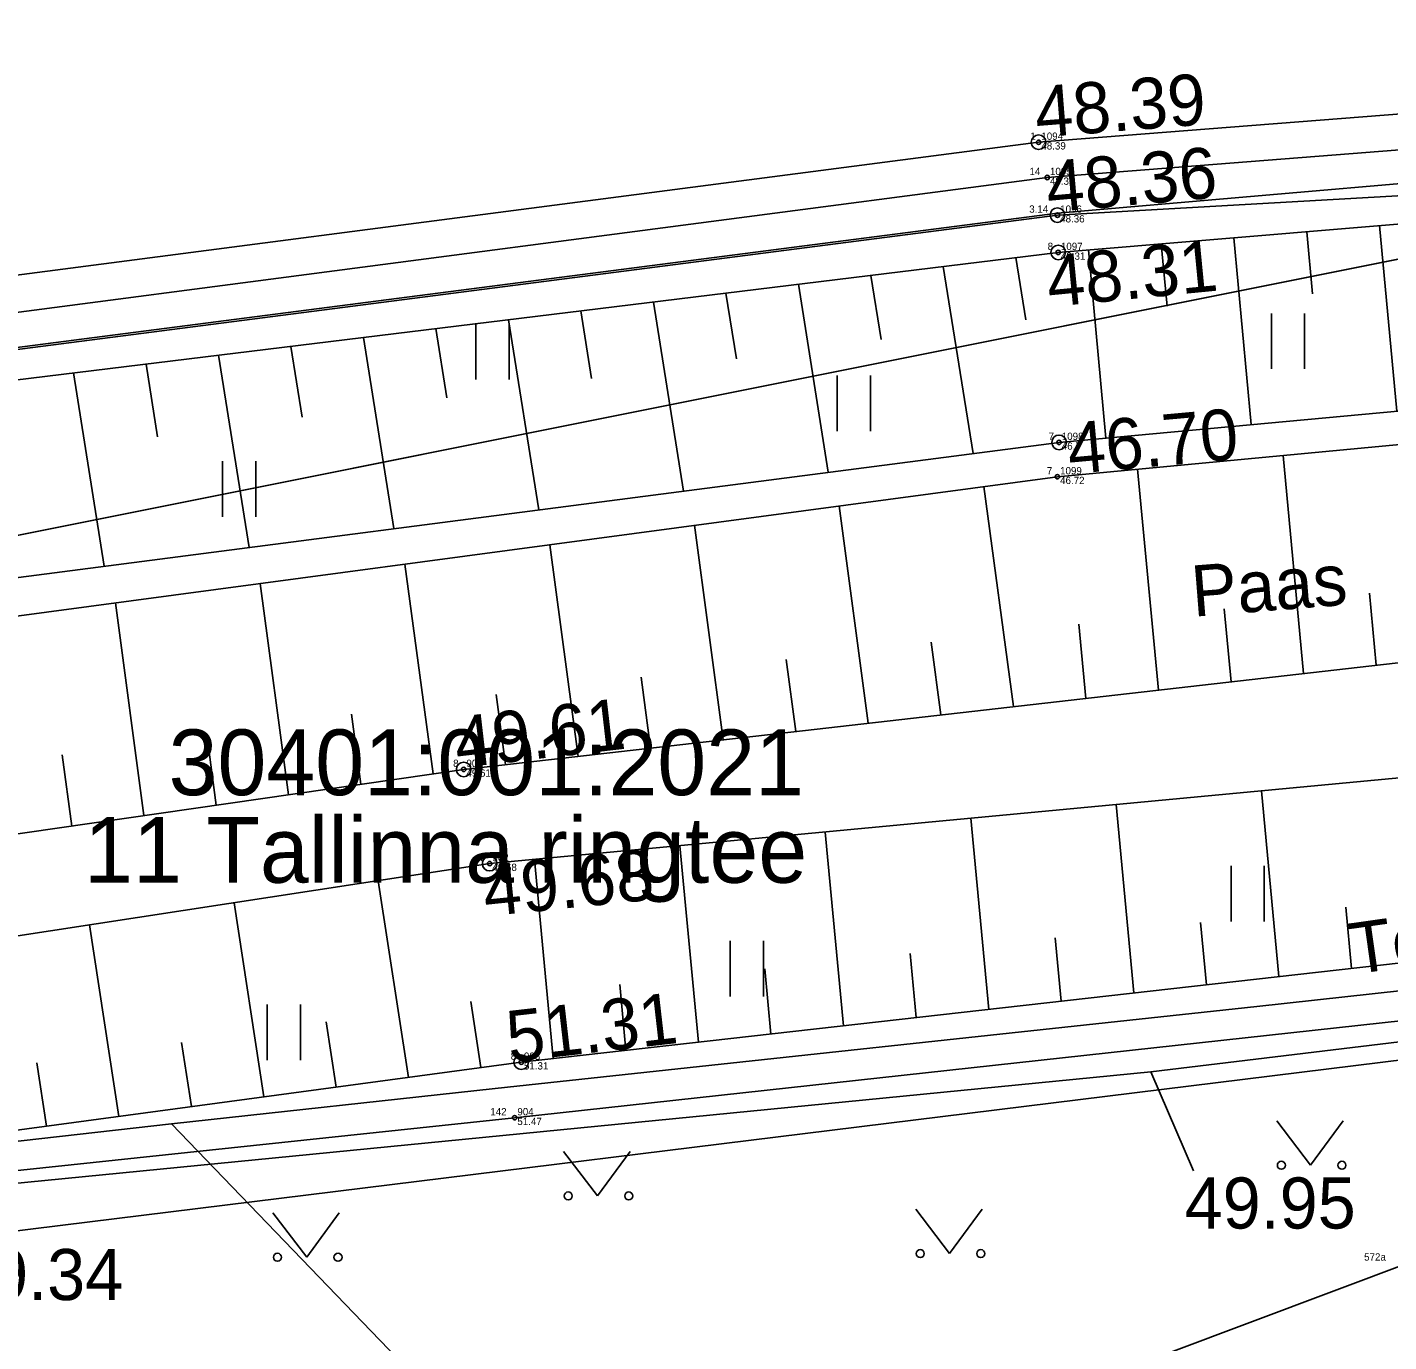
# Model space of a CAD drawing. Extents: x 543497 to 552146, y 6567125 to 6579845.
# Drawn here: x 546585.95 to 546604.6, y 6577772.23 to 6577790.24 of the extents above; entities that cross this region are included whole.
import ezdxf

# ---------------------------------------------------------------- set-up
doc = ezdxf.new("R2010")
doc.units = 0
for name, color, linetype in [('xref_Kangru tee 1_geodeesia$0$ABIJOONIS', 7, 'Continuous'), ('xref_Kangru tee 1_geodeesia$0$AED', 7, 'Continuous'), ('xref_Kangru tee 1_geodeesia$0$HALJASTUS', 7, 'Continuous'), ('xref_Kangru tee 1_geodeesia$0$korgus-EH2000', 7, 'Continuous'), ('xref_Kangru tee 1_geodeesia$0$Liiklus', 7, 'Continuous'), ('xref_Kangru tee 1_geodeesia$0$mootkood', 7, 'Continuous'), ('xref_Kangru tee 1_geodeesia$0$MOOTKORG-eh2000', 7, 'Continuous'), ('xref_Kangru tee 1_geodeesia$0$mootmpunkt', 7, 'Continuous'), ('xref_Kangru tee 1_geodeesia$0$MOOTNR', 7, 'Continuous'), ('xref_Kangru tee 1_geodeesia$0$MPOHULIIN', 7, 'Continuous'), ('xref_Kangru tee 1_geodeesia$0$PIIR', 7, 'Continuous'), ('xref_Kangru tee 1_geodeesia$0$RELJEEF', 7, 'Continuous'), ('xref_Kangru tee 1_geodeesia$0$SITRASS', 7, 'Continuous'), ('xref_Kangru tee 1_geodeesia$0$TEE', 7, 'Continuous')]:
    doc.layers.add(name, color=color, linetype=linetype)

# ---------------------------------------------------------------- blocks, each defined once
blk = doc.blocks.new('xref_Kangru tee 1_geodeesia$0$MURU')
for p, q in [((-0.927, 1.213), (0, 0)), ((0, 0), (0.891, 1.213))]:
    blk.add_line(p, q)
for centre in [(-0.802, 0), (0.856, 0)]:
    blk.add_circle(centre, 0.11)
blk = doc.blocks.new('xref_Kangru tee 1_geodeesia$0$hein')
for p, q in [((-0.455, 0.761), (-0.455, -0.761)), ((0.455, 0.761), (0.455, -0.761))]:
    blk.add_line(p, q)

msp = doc.modelspace()

# ---------------------------------------------------------------- linework, layer by layer
at = {"layer": 'xref_Kangru tee 1_geodeesia$0$ABIJOONIS'}
msp.add_lwpolyline([(546601.337, 6577775.932), (546601.923, 6577774.573)], dxfattribs=at)
at = {"layer": 'xref_Kangru tee 1_geodeesia$0$AED'}
msp.add_lwpolyline([(546619.888, 6577778.288), (546609.506, 6577777.149), (546592.626, 6577775.302), (546575.912, 6577773.527), (546572.329, 6577772.88), (546567.646, 6577771.651), (546545.991, 6577765.945)], dxfattribs=at)
at = {"layer": 'xref_Kangru tee 1_geodeesia$0$korgus-EH2000'}
for centre in [(546599.801, 6577788.666), (546600.059, 6577787.667), (546600.069, 6577787.156), (546600.081, 6577784.554), (546591.928, 6577780.074), (546592.284, 6577778.783), (546592.716, 6577776.063)]:
    msp.add_circle(centre, 0.1, dxfattribs=at)
at = {"layer": 'xref_Kangru tee 1_geodeesia$0$Liiklus'}
for points in [[(546721.913, 6577774.924), (546704.498, 6577780.481), (546687.619, 6577784.545), (546672.912, 6577787.228), (546667.133, 6577788), (546648.703, 6577789.664), (546634.507, 6577790.018), (546619.416, 6577789.618), (546613.24, 6577789.23), (546599.919, 6577788.183), (546580.395, 6577785.626), (546558.693, 6577781.92), (546538.215, 6577778.009)], [(546538.26, 6577777.571), (546558.77, 6577781.533), (546580.893, 6577785.218), (546600.058, 6577787.695), (546613.274, 6577788.837)]]:
    msp.add_lwpolyline(points, dxfattribs=at)
at = {"layer": 'xref_Kangru tee 1_geodeesia$0$mootmpunkt'}
for centre in [(546599.801, 6577788.666), (546599.919, 6577788.183), (546600.059, 6577787.667), (546600.069, 6577787.156), (546600.081, 6577784.554), (546600.058, 6577784.083), (546591.928, 6577780.074), (546592.284, 6577778.783), (546592.716, 6577776.063), (546592.626, 6577775.302)]:
    msp.add_circle(centre, 0.03, dxfattribs=at)
at = {"layer": 'xref_Kangru tee 1_geodeesia$0$MPOHULIIN'}
msp.add_lwpolyline([(546592.592, 6577768.702), (546604.965, 6577773.353), (546609.288, 6577765.908)], dxfattribs=at)
at = {"layer": 'xref_Kangru tee 1_geodeesia$0$PIIR'}
for points in [[(546508.03, 6577841.48), (546527.76, 6577842.6), (546535.64, 6577829.79), (546540.71, 6577817.81), (546551.12, 6577809.99), (546561.59, 6577802.16), (546622.52, 6577814.88), (546633.51, 6577792.62), (546608.95, 6577787.91), (546573.78, 6577780.87), (546521.59, 6577770.69), (546316.12, 6577725.86), (546173.38, 6577691.06), (546034.23, 6577654.21), (545899.95, 6577611.29), (545780.54, 6577566.57), (545623.97, 6577499.02), (545555.77, 6577467.67), (545385.83, 6577376.92), (545249.19, 6577295.85), (545250.22, 6577289.9), (544980.83, 6577118.49)], [(546608.95, 6577787.91), (546613.94, 6577777.23), (546573.57, 6577772.24), (546573.78, 6577780.87), (546608.95, 6577787.91)], [(546572.44, 6577729.89), (546573.57, 6577772.24), (546613.94, 6577777.23), (546617.58, 6577769.56), (546644.8, 6577768), (546649.32, 6577758.15), (546629.37, 6577744.28), (546606.33, 6577728.26), (546597.82, 6577742.14), (546572.44, 6577729.89)]]:
    msp.add_lwpolyline(points, dxfattribs=at)
at = {"layer": 'xref_Kangru tee 1_geodeesia$0$RELJEEF'}
for p, q in [((546604.469, 6577787.523), (546604.704, 6577784.982)), ((546601.479, 6577787.274), (546601.559, 6577786.418)), ((546602.476, 6577787.357), (546602.713, 6577784.798)), ((546603.472, 6577787.44), (546603.551, 6577786.59)), ((546599.489, 6577787.085), (546599.624, 6577786.231)), ((546600.483, 6577787.191), (546600.721, 6577784.613)), ((546598.496, 6577786.963), (546598.904, 6577784.401)), ((546596.511, 6577786.72), (546596.921, 6577784.144)), ((546597.503, 6577786.842), (546597.643, 6577785.965)), ((546595.518, 6577786.599), (546595.662, 6577785.698)), ((546593.533, 6577786.356), (546593.68, 6577785.431)), ((546594.526, 6577786.477), (546594.938, 6577783.887)), ((546592.54, 6577786.234), (546592.955, 6577783.63)), ((546590.555, 6577785.991), (546590.972, 6577783.372)), ((546591.548, 6577786.113), (546591.699, 6577785.164)), ((546589.563, 6577785.869), (546589.717, 6577784.898)), ((546587.578, 6577785.626), (546587.736, 6577784.631)), ((546588.57, 6577785.748), (546588.989, 6577783.115)), ((546586.585, 6577785.505), (546587.006, 6577782.858)), ((546603.429, 6577781.388), (546603.148, 6577784.374)), ((546601.442, 6577781.161), (546601.157, 6577784.187)), ((546599.455, 6577780.934), (546599.052, 6577783.948)), ((546597.468, 6577780.707), (546597.07, 6577783.683)), ((546595.481, 6577780.48), (546595.088, 6577783.418)), ((546593.494, 6577780.253), (546593.106, 6577783.152)), ((546591.509, 6577780.013), (546591.124, 6577782.887)), ((546589.529, 6577779.727), (546589.142, 6577782.622)), ((546604.423, 6577781.501), (546604.33, 6577782.49)), ((546587.55, 6577779.441), (546587.159, 6577782.356)), ((546602.436, 6577781.274), (546602.341, 6577782.276)), ((546600.449, 6577781.047), (546600.353, 6577782.062)), ((546598.462, 6577780.82), (546598.328, 6577781.819)), ((546596.475, 6577780.593), (546596.343, 6577781.579)), ((546594.488, 6577780.366), (546594.357, 6577781.339)), ((546592.501, 6577780.139), (546592.372, 6577781.099)), ((546590.519, 6577779.87), (546590.39, 6577780.832)), ((546588.539, 6577779.584), (546588.41, 6577780.553)), ((546586.56, 6577779.298), (546586.429, 6577780.273)), ((546603.092, 6577777.235), (546602.852, 6577779.78)), ((546601.105, 6577777.011), (546600.861, 6577779.592)), ((546599.117, 6577776.786), (546598.871, 6577779.404)), ((546597.13, 6577776.562), (546596.88, 6577779.216)), ((546595.143, 6577776.337), (546594.889, 6577779.029)), ((546593.155, 6577776.113), (546592.898, 6577778.841)), ((546591.172, 6577775.855), (546590.759, 6577778.549)), ((546589.19, 6577775.588), (546588.783, 6577778.247)), ((546604.086, 6577777.347), (546604.006, 6577778.189)), ((546602.098, 6577777.123), (546602.018, 6577777.977)), ((546587.208, 6577775.321), (546586.806, 6577777.944)), ((546600.111, 6577776.898), (546600.029, 6577777.765)), ((546598.124, 6577776.674), (546598.041, 6577777.553)), ((546596.136, 6577776.449), (546596.052, 6577777.34)), ((546594.149, 6577776.225), (546594.064, 6577777.128)), ((546592.163, 6577775.989), (546592.025, 6577776.893)), ((546590.181, 6577775.721), (546590.044, 6577776.614)), ((546588.199, 6577775.454), (546588.064, 6577776.335)), ((546586.217, 6577775.187), (546586.084, 6577776.056))]:
    msp.add_line(p, q, dxfattribs=at)
for points in [[(546538.34, 6577776.988), (546558.87, 6577780.697), (546581.001, 6577784.821), (546600.069, 6577787.156), (546619.252, 6577788.758)], [(546538.814, 6577774.564), (546558.883, 6577778.247), (546581.357, 6577782.125), (546600.081, 6577784.554), (546618.535, 6577786.262), (546633.012, 6577786.921), (546648.115, 6577786.579), (546666.374, 6577784.262), (546672.405, 6577783.73), (546686.612, 6577781.238), (546689.643, 6577780.706), (546693.637, 6577779.753), (546703.929, 6577777.342), (546710.71, 6577775.098), (546720.871, 6577771.555)], [(546538.896, 6577773.872), (546559.049, 6577777.65), (546581.571, 6577781.608), (546600.058, 6577784.083), (546618.575, 6577785.829), (546632.878, 6577786.269), (546648.145, 6577785.891), (546666.337, 6577783.931), (546672.337, 6577783.228), (546686.505, 6577780.733), (546689.529, 6577780.165), (546693.523, 6577779.183), (546703.735, 6577776.88), (546710.628, 6577774.799), (546720.7, 6577771.177)], [(546554.904, 6577773.96), (546559.746, 6577774.952), (546563.529, 6577775.486), (546566.104, 6577776.076), (546569.451, 6577776.73), (546575.285, 6577777.669), (546591.928, 6577780.074), (546609.002, 6577782.024), (546618.326, 6577782.861), (546622.722, 6577782.991), (546628.579, 6577783.379), (546640.222, 6577783.284), (546642.311, 6577782.972), (546644.296, 6577782.453), (546645.105, 6577782.242), (546655.773, 6577781.108), (546661.524, 6577780.531), (546663.681, 6577779.627)], [(546663.681, 6577779.627), (546661.025, 6577779.482), (546655.667, 6577780.24), (546645.195, 6577781.158), (546642.472, 6577782.453), (546639.822, 6577782.844), (546628.438, 6577782.653), (546623.553, 6577781.976), (546622.345, 6577781.625), (546621.629, 6577780.852), (546620.046, 6577780.644), (546609.199, 6577780.378), (546592.284, 6577778.783), (546575.483, 6577776.209), (546566.953, 6577773.885), (546564.502, 6577773.16), (546560.282, 6577772.223), (546558.324, 6577771.967), (546554.183, 6577771.468), (546550.857, 6577770.53)], [(546550.727, 6577769.706), (546551.249, 6577769.491), (546567.458, 6577772.217), (546575.824, 6577773.787), (546592.716, 6577776.063), (546609.093, 6577777.913), (546620.403, 6577778.527), (546622.24, 6577778.664), (546623.137, 6577779.453), (546623.473, 6577780.609), (546628.431, 6577781.294), (546639.632, 6577780.958), (546641.087, 6577780.8), (546642.154, 6577779.459), (546644.484, 6577778.868), (546654.742, 6577777.987), (546663.525, 6577777.379)]]:
    msp.add_lwpolyline(points, dxfattribs=at)
at = {"layer": 'xref_Kangru tee 1_geodeesia$0$SITRASS'}
for points in [[(546616.772, 6577777.542), (546615.216, 6577778.191), (546602.787, 6577776.827), (546592.36, 6577775.701), (546587.927, 6577775.219), (546580.777, 6577774.412), (546573.919, 6577773.607), (546573.241, 6577772.489), (546571.76, 6577771.98)], [(546535.945, 6577765.191), (546545.774, 6577767.54), (546561.492, 6577770.597), (546573.177, 6577772.732), (546581.496, 6577773.983), (546601.337, 6577775.932), (546614.05, 6577777.466), (546620.283, 6577777.55), (546631.954, 6577777.234), (546639.759, 6577775.901), (546642.232, 6577774.863), (546647.939, 6577768.847), (546651.396, 6577764.746), (546652.558, 6577762.284)], [(546535.945, 6577765.191), (546545.774, 6577767.54), (546561.492, 6577770.597), (546573.177, 6577772.732), (546581.496, 6577773.983), (546601.337, 6577775.932), (546614.05, 6577777.466), (546620.283, 6577777.55), (546631.954, 6577777.234), (546639.759, 6577775.901)], [(546587.927, 6577775.219), (546591.733, 6577771.265), (546594.538, 6577767.613), (546594.446, 6577766.8), (546594.155, 6577766.441)]]:
    msp.add_lwpolyline(points, dxfattribs=at)
at = {"layer": 'xref_Kangru tee 1_geodeesia$0$TEE'}
for points in [[(546538.072, 6577778.474), (546558.355, 6577782.483), (546580.018, 6577786.09), (546599.801, 6577788.666), (546619.258, 6577790.187), (546634.544, 6577790.675), (546648.905, 6577790.198), (546667.188, 6577788.59), (546673.08, 6577787.807), (546687.848, 6577785.135), (546704.62, 6577781.061), (546722.283, 6577775.399)], [(546704.364, 6577779.548), (546687.303, 6577783.754), (546672.831, 6577786.155), (546666.989, 6577786.944), (546648.576, 6577788.953), (546634.52, 6577789.12), (546619.252, 6577788.758), (546600.059, 6577787.667), (546580.898, 6577785.19), (546558.777, 6577781.504), (546538.268, 6577777.542)]]:
    msp.add_lwpolyline(points, dxfattribs=at)

# ---------------------------------------------------------------- block references
at = {"layer": 'xref_Kangru tee 1_geodeesia$0$HALJASTUS', "xscale": 0.5, "yscale": 0.5}
for name, p in [('xref_Kangru tee 1_geodeesia$0$hein', (546592.324, 6577785.798)), ('xref_Kangru tee 1_geodeesia$0$hein', (546603.216, 6577785.94)), ('xref_Kangru tee 1_geodeesia$0$hein', (546597.272, 6577785.088)), ('xref_Kangru tee 1_geodeesia$0$hein', (546588.853, 6577783.914)), ('xref_Kangru tee 1_geodeesia$0$hein', (546602.664, 6577778.372)), ('xref_Kangru tee 1_geodeesia$0$hein', (546595.806, 6577777.343)), ('xref_Kangru tee 1_geodeesia$0$hein', (546589.464, 6577776.471)), ('xref_Kangru tee 1_geodeesia$0$MURU', (546603.526, 6577774.651)), ('xref_Kangru tee 1_geodeesia$0$MURU', (546593.76, 6577774.231)), ('xref_Kangru tee 1_geodeesia$0$MURU', (546598.581, 6577773.441)), ('xref_Kangru tee 1_geodeesia$0$MURU', (546589.779, 6577773.391))]:
    msp.add_blockref(name, p, dxfattribs=at)

# ---------------------------------------------------------------- texts
at = {"layer": 'xref_Kangru tee 1_geodeesia$0$ABIJOONIS'}
for s, p in [('49.95', (546601.801, 6577773.784)), ('49.34', (546584.923, 6577772.804))]:
    msp.add_text(s, height=0.7, dxfattribs=at).set_placement(p)
at = {"layer": 'xref_Kangru tee 1_geodeesia$0$HALJASTUS'}
msp.add_text('Paas', height=0.7, rotation=4.5305, dxfattribs=at).set_placement((546601.92, 6577782.165))
at = {"layer": 'xref_Kangru tee 1_geodeesia$0$korgus-EH2000'}
for s, rotation, p in [(' 48.39 ', 4.5305, (546599.517, 6577788.708)), (' 48.36 ', 5.0492, (546599.675, 6577787.681)), (' 48.31 ', 5.568, (546599.687, 6577786.383)), (' 46.70 ', 5.1685, (546599.968, 6577784.094)), (' 49.61 ', 6.5994, (546591.584, 6577780.061)), (' 49.68 ', 5.7391, (546591.969, 6577778.034)), (' 51.31 ', 6.5426, (546592.298, 6577776.032))]:
    msp.add_text(s, height=0.7, rotation=rotation, dxfattribs=at).set_placement(p)
at = {"layer": 'xref_Kangru tee 1_geodeesia$0$mootkood'}
for s, p in [(' 1', (546599.649, 6577788.699)), (' 14', (546599.638, 6577788.216)), (' 3.14', (546599.635, 6577787.7)), (' 8', (546599.888, 6577787.189)), (' 7', (546599.9, 6577784.587)), (' 7', (546599.877, 6577784.116)), (' 8', (546591.747, 6577780.107)), (' 7', (546592.103, 6577778.816)), (' 8', (546592.535, 6577776.096)), (' 142', (546592.255, 6577775.335)), (' 572a', (546604.221, 6577773.345))]:
    msp.add_text(s, height=0.1, dxfattribs=at).set_placement(p)
at = {"layer": 'xref_Kangru tee 1_geodeesia$0$MOOTKORG-eh2000'}
for s, p in [(' 48.39', (546599.801, 6577788.566)), (' 48.35', (546599.919, 6577788.083)), (' 48.36', (546600.059, 6577787.567)), (' 48.31', (546600.069, 6577787.056)), (' 46.7', (546600.081, 6577784.454)), (' 46.72', (546600.058, 6577783.983)), (' 49.61', (546591.928, 6577779.974)), (' 49.68', (546592.284, 6577778.683)), (' 51.31', (546592.716, 6577775.963)), (' 51.47', (546592.626, 6577775.202))]:
    msp.add_text(s, height=0.1, dxfattribs=at).set_placement(p)
at = {"layer": 'xref_Kangru tee 1_geodeesia$0$MOOTNR'}
for s, p in [(' 1094', (546599.801, 6577788.699)), (' 1095', (546599.919, 6577788.216)), (' 1096', (546600.059, 6577787.7)), (' 1097', (546600.069, 6577787.189)), (' 1098', (546600.081, 6577784.587)), (' 1099', (546600.058, 6577784.116)), (' 901', (546591.928, 6577780.107)), (' 902', (546592.284, 6577778.816)), (' 903', (546592.716, 6577776.096)), (' 904', (546592.626, 6577775.335))]:
    msp.add_text(s, height=0.1, dxfattribs=at).set_placement(p)
at = {"layer": 'xref_Kangru tee 1_geodeesia$0$PIIR'}
for s, p in [('30401:001:2021', (546587.887, 6577779.721)), ('11 Tallinna ringtee', (546586.73, 6577778.521))]:
    msp.add_text(s, height=0.9, dxfattribs=at).set_placement(p)
at = {"layer": 'xref_Kangru tee 1_geodeesia$0$SITRASS'}
msp.add_text('Telia Eesti AS', height=0.7, rotation=8.0491, dxfattribs=at).set_placement((546604.116, 6577777.265))

doc.saveas('drawing.dxf')
